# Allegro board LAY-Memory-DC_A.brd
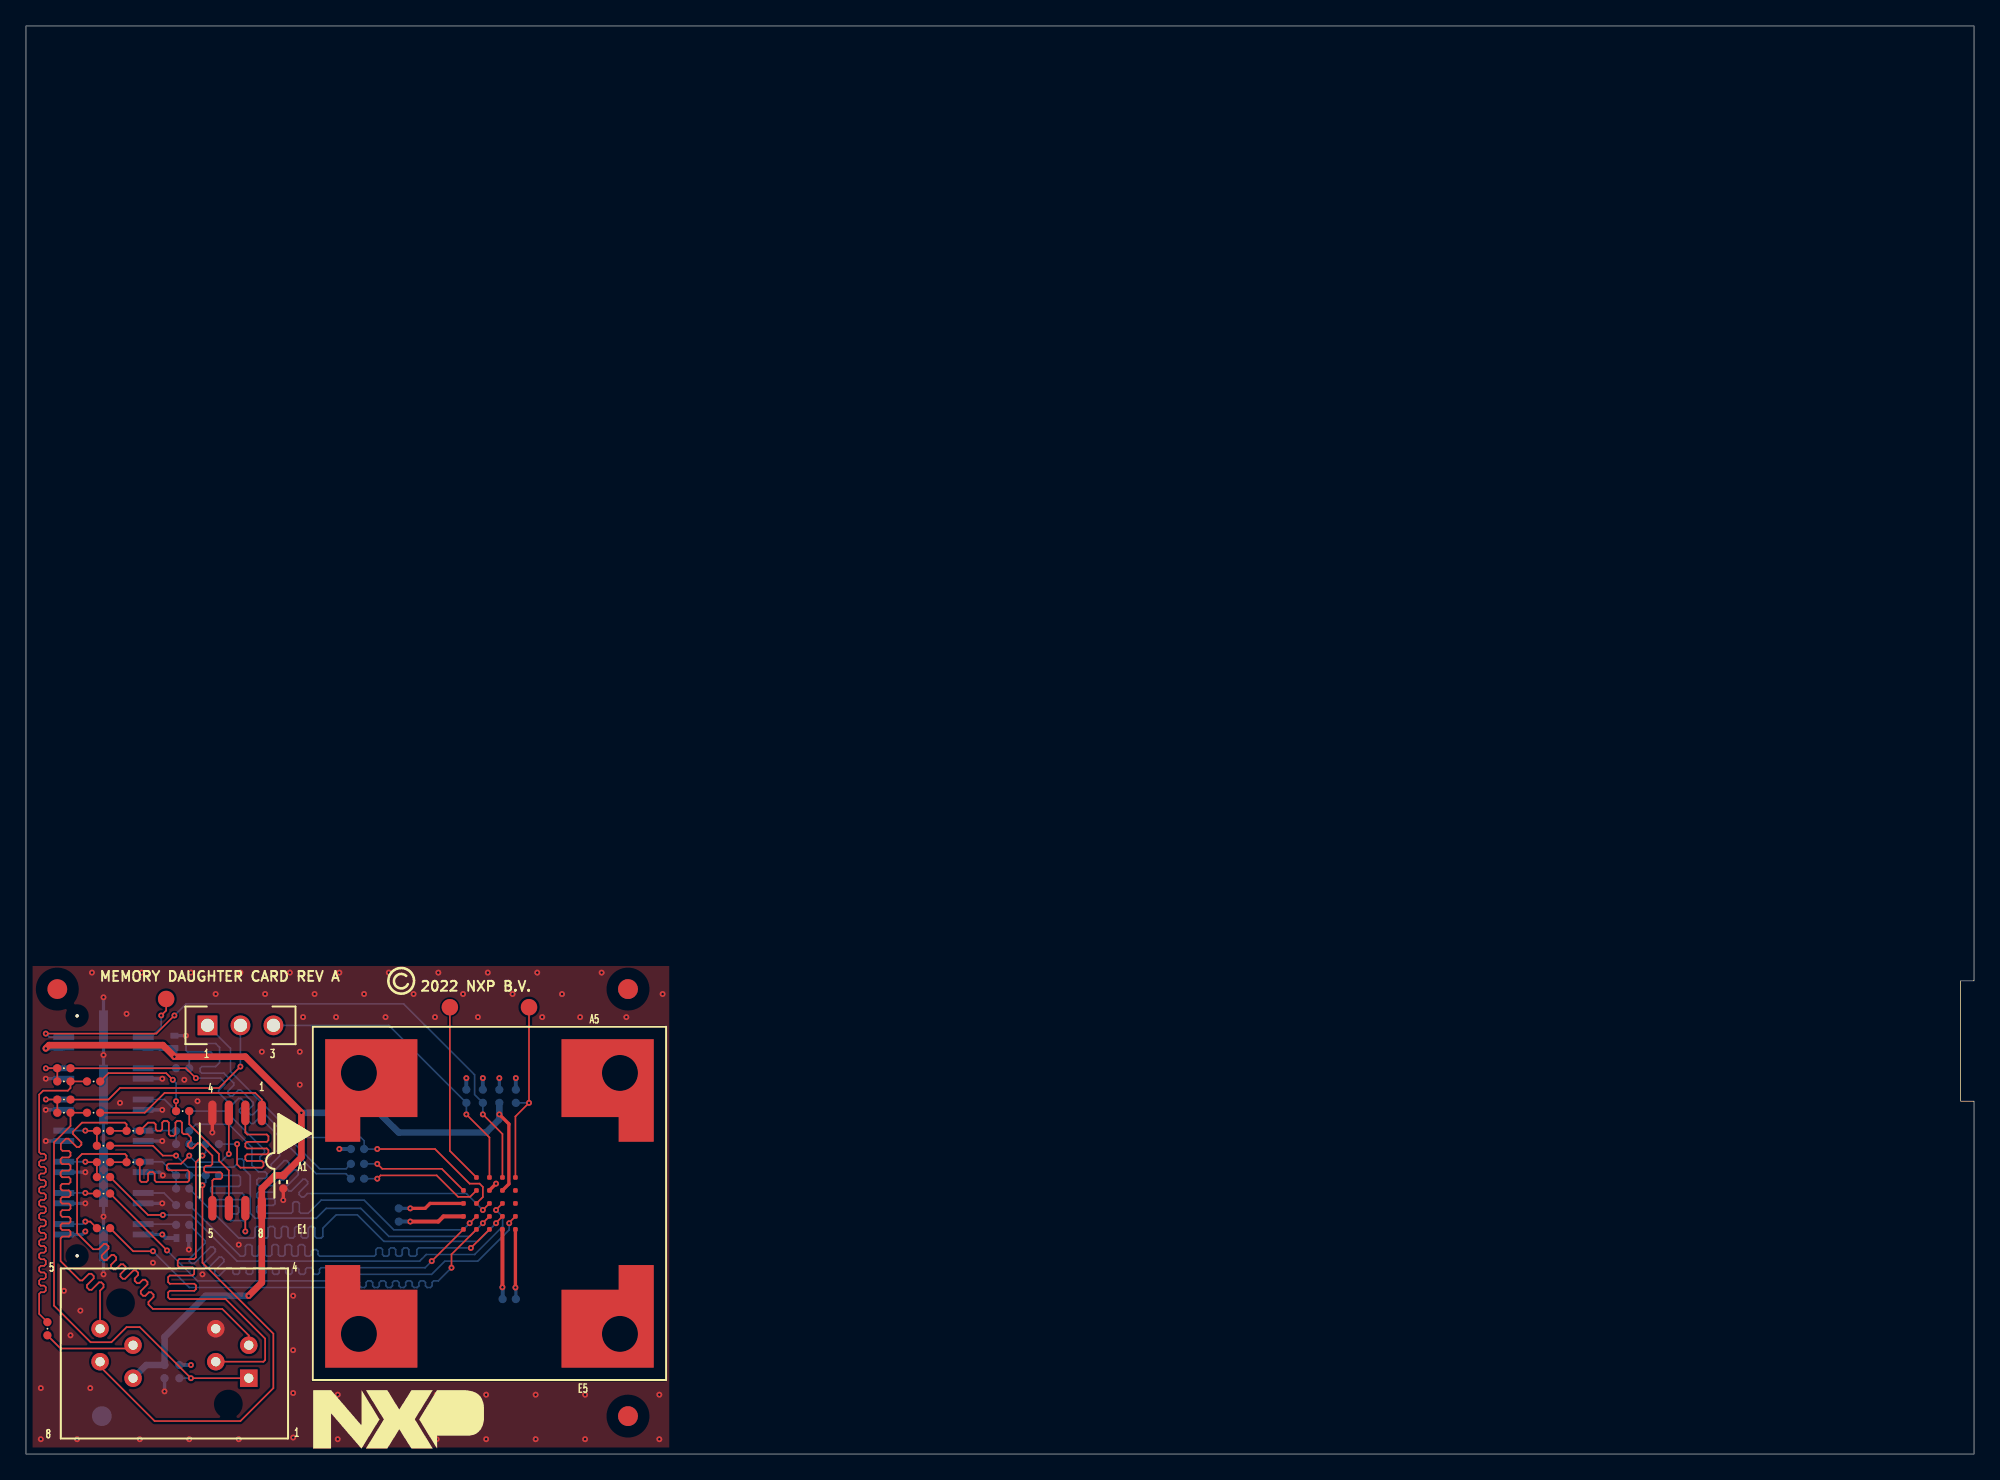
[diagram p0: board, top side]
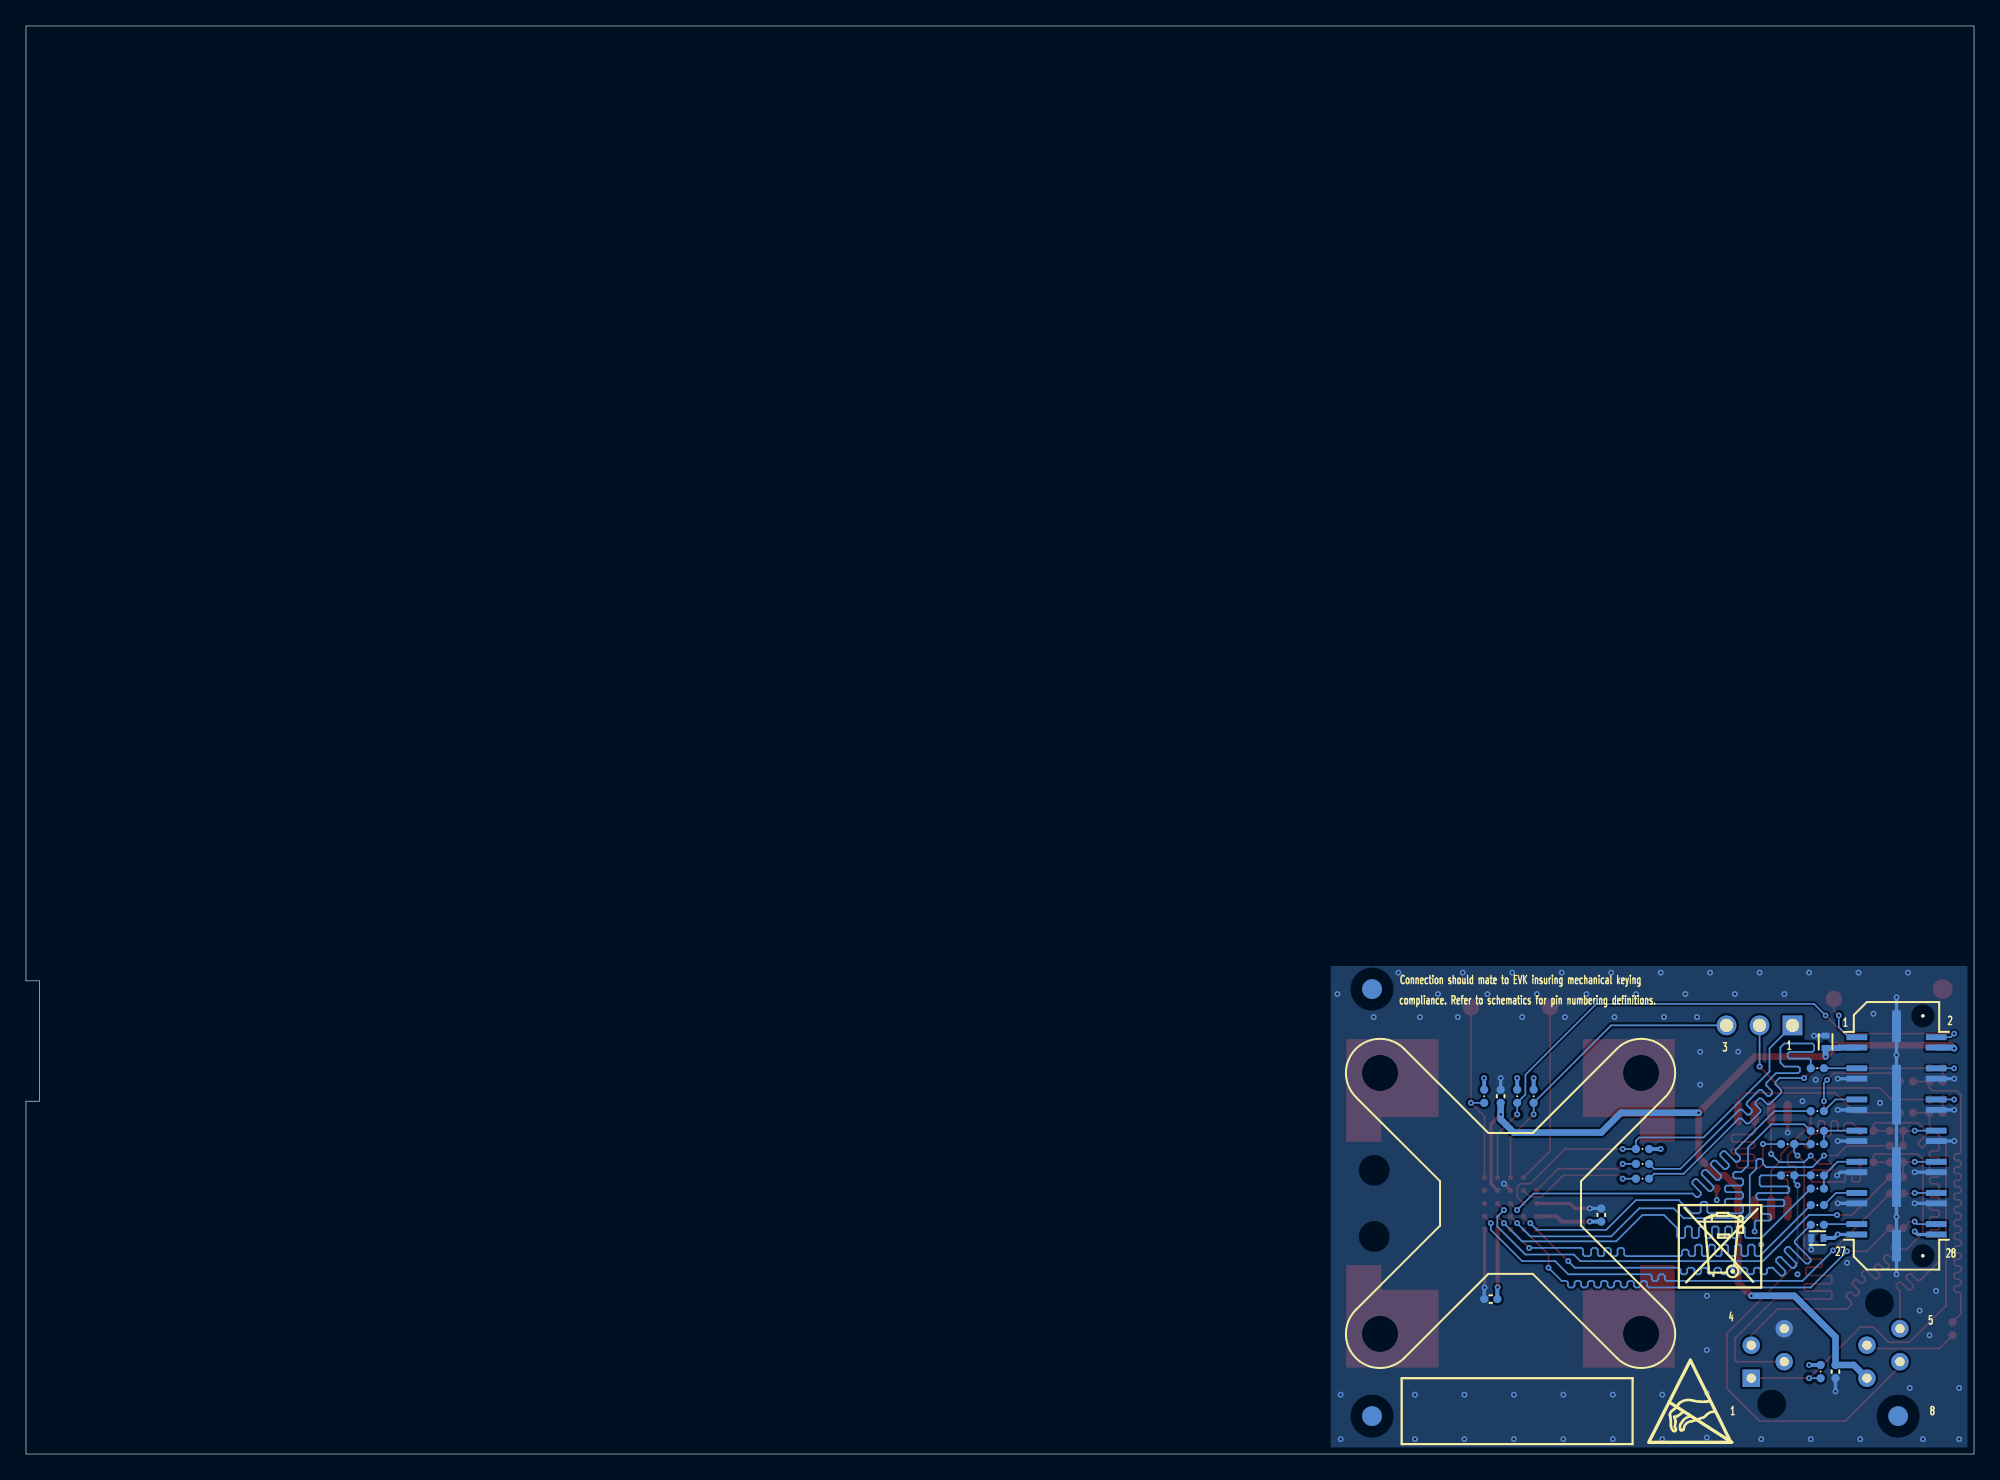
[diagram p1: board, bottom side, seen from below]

Outline 150 x 110 mm; copper layers: TOP, GND, POWER, BOTTOM. Coordinates in mm from the lower left corner of the outline.
Outline path: 0,110 150,110 150,36.45 148.97,36.45 148.97,27.18 150,27.18 150,0 0,0 0,110

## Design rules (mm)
constraint set DEFAULT: min track width 0.127
net group POWER: nets VDD_MEM VPP
net group SPI_D4: nets SPI_D4 SPI_D4_BGA24
net group SPI_D5: nets SPI_D5 SPI_D5_BGA24
net group SPI_D6: nets SPI_D6 SPI_D6_BGA24
net group SPI_D7: nets SPI_D7 SPI_D7_BGA24
net group SPI_DQS: nets SPI_DQS SPI_DQS_BGA24
net group 3W: nets RSTO#
net group SPI_CLK: nets N50940402 N50947464 N50953647 SPI_CLK SPI_CLK_BGA24 SPI_CLK_SD SPI_CLK_SOIC
net group SPI_CLKN: nets N50940399 SPI_CLKN SPI_CLKN_BGA24
net group SPI_CONN: nets CS_RAMN CSN_FLASH INT# SPI_RESETN
net group SPI_CSN_SD: nets SPI_CS_BGA24 SPI_CSN SPI_CSN_SD SPI_CSN_SOIC
net group SPI_D0: nets SPI_D0 SPI_D0_BGA24 SPI_D0_SD SPI_D0_SOIC
net group SPI_D1: nets SPI_D1 SPI_D1_BGA24 SPI_D1_SD SPI_D1_SOIC
net group SPI_D2: nets SPI_D2 SPI_D2_BGA24 SPI_D2_SD SPI_D2_SOIC
net group SPI_D3: nets SPI_D3 SPI_D3_BGA24 SPI_D3_SD SPI_D3_SOIC

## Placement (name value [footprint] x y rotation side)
C1  10uF  [CC0402_TOL0P2]  11.43 31.75 90 bottom
C2  10uF  [CC0402_TOL0P2]  12.06 16.64 0 bottom
C3  0.1UF  [CC0402_25]  28.7 18.41 90 bottom
C4  0.1UF  [CC0402_25]  37.21 11.94 0 bottom
C5  0.1UF  [CC0402_25]  36.45 27.56 90 bottom
C6  0.1UF  [CC0402_25]  10.67 6.35 270 bottom
C7  0.1UF  [CC0402_25]  19.81 20.95 270 top
J1  CON 2X14  [CON_28M_0P8_SMT]  5.97 24.51 270 bottom
JP1  HDR TH 1X3  [HDR103]  13.98 33.02 90 top
NOREF  -  []  9.88 31.15 90 top
NOREF#2  -  []  -4.81 5.8 0 top
NOREF#3  -  []  9.02 24.11 90 top
NOREF#4  -  []  33.69 17.3 0 top
NOREF#5  -  [unnamed#2]  2.41 35.81 0 top
NOREF#6  -  []  -2.26 -18.65 90 top
NOREF#7  -  []  30.44 17.52 0 top
NOREF#8  -  []  9.88 31.15 0 top
NOREF#9  -  []  11.59 16.64 0 top
NOREF#10  -  []  5.97 27.69 90 top
NOREF#11  -  []  22.12 0.42 0 top
NOREF#12  -  []  25.64 9.25 0 top
NOREF#13  -  []  2.91 16.91 0 top
NOREF#14  -  []  5.97 16.07 90 top
NOREF#15  -  []  11.43 31.28 90 top
NOREF#16  -  []  0 0 90 top
NOREF#17  -  []  50.51 1.01 90 top
NOREF#18  -  []  3.94 33.75 0 top
NOREF#19  -  [unnamed#2]  46.35 35.81 0 top
NOREF#20  -  []  -2.26 6.65 0 top
NOREF#21  -  []  11.47 16.99 0 top
NOREF#22  -  []  22.11 28.42 90 top
NOREF#23  -  []  -4.81 -21.2 90 top
NOREF#24  -  []  3.94 15.27 90 top
NOREF#25  -  []  3.94 15.27 90 top
NOREF#26  -  []  5.97 21.34 90 top
NOREF#27  -  []  2.86 29.42 0 top
NOREF#28  -  []  12.66 16.29 90 top
NOREF#29  -  []  0 0 0 top
NOREF#30  -  []  28.89 36.42 0 top
NOREF#31  -  []  45.74 9.25 90 top
NOREF#32  -  []  25.19 16.75 90 top
NOREF#33  -  []  25.19 16.75 0 top
NOREF#34  -  []  -219.71 -78.11 0 top
NOREF#35  -  []  9.02 16.91 90 top
NOREF#36  -  [unnamed#2]  46.35 2.92 0 top
NOREF#37  -  []  0 0.03 0 top
NOREF#38  -  [unnamed#2]  46.35 2.92 180 bottom
NOREF#39  -  []  22.73 12.83 180 bottom
NOREF#40  -  [unnamed#2]  46.35 35.81 180 bottom
NOREF#41  -  []  44.07 0.76 180 bottom
NOREF#42  -  []  25.02 0.9 180 bottom
NOREF#43  -  [unnamed#2]  5.84 2.92 180 bottom
R1  4.7K  [RC0402_25]  35.18 27.56 90 bottom
R2  4.7K  [RC0402_25]  25.53 23.5 180 bottom
R3  4.7K  [RC0402_25]  37.72 27.56 90 bottom
R4  4.7K  [RC0402_25]  33.91 27.56 90 bottom
R5  0  [RC0402_25]  25.53 21.21 180 bottom
R6  0  [RC0402_25]  25.53 22.35 180 bottom
R7  0  [RC0402_25]  1.65 9.65 90 top
R8  0  [RC0402_25]  12.06 26.42 180 top
R9  0  [RC0402_25]  2.92 27.3 180 top
R10  0  [RC0402_25]  2.92 29.72 180 top
R11  0  [RC0402_25]  12.06 29.72 180 bottom
R12  0  [RC0402_25]  12.06 26.42 180 bottom
R13  0  [RC0402_25]  5.97 23.75 180 top
R14  0  [RC0402_25]  12.06 24.89 180 bottom
R15  0  [RC0402_25]  5.97 21.34 180 top
R16  0  [RC0402_25]  12.06 20.45 180 bottom
R17  0  [RC0402_25]  5.97 20.07 180 top
R18  0  [RC0402_25]  12.06 19.18 180 bottom
R19  0  [RC0402_25]  5.97 17.4 180 top
R20  0  [RC0402_25]  12.06 17.65 180 bottom
R21  0  [RC0402_25]  2.92 28.7 180 top
R22  0  [RC0402_25]  2.92 26.29 180 top
R23  0  [RC0402_25]  5.97 24.89 180 top
R24  0  [RC0402_25]  12.06 23.88 180 bottom
R25  0  [RC0402_25]  5.97 22.48 180 top
R26  0  [RC0402_25]  12.06 21.46 180 bottom
R27  0  [RC0402_25]  5.21 28.7 180 top
R28  0  [RC0402_25]  5.21 26.29 180 top
R29  0  [RC0402_25]  8.26 24.89 180 top
R30  0  [RC0402_25]  14.35 23.88 180 bottom
R31  0  [RC0402_25]  8.26 22.48 180 top
R32  0  [RC0402_25]  14.35 21.46 180 bottom
R33  4.7K  [RC0402_25]  11.81 6.35 90 bottom
TP1  -  [TPAD_050]  10.79 35.05 0 top
TP2  -  [TPAD_050]  32.64 34.42 270 top
TP3  -  [TPAD_050]  38.73 34.42 270 top
U1  SUBASSEMBLY  [SKT_BGA24_1MM_25X25MM]  35.69 19.3 0 top
U2  SKT_SOP8+IS25WP064AJBLE  [SKT8_SOP_1P27_TH]  17.16 5.84 0 top
U3  IS25WP064AJBLE  [SO8-25X75-200]  16.26 22.61 180 top

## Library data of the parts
C1 C2 = CAP_NP: signal model: DEFAULT_CAPACITOR_1e+07pF_2_1
C3-C7 = CAP_NP: signal model: DEFAULT_CAPACITOR_100000pF_2_1
J1 = QSE_014_DP
JP1 = CONN_HDR_3X1
R1-R4 = RES
R5-R32 = RES: signal model: DEFAULT_RESISTOR_0.001OHM_2_1
R33 = RES: signal model: DEFAULT_RESISTOR_4700OHM_2_1
TP1-TP3 = TEST POINT L
U1 = MT35XU512ABA1G12
U2 U3 = 25WP_8P

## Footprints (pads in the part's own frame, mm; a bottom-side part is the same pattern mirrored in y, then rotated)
CC0402_25
  round 0.635 smd: 1(-0.508,0) 2(0.508,0)
CC0402_TOL0P2
  rect 0.457x0.61 smd: 1(-0.475,0) 2(0.475,0)
CON_28M_0P8_SMT
  round 0.254 hole 1.016 unplated: (-9.24,2.03) (9.24,2.03)
  rect 0.457x1.6 smd: 1(-7.6,-3.055) 2(-7.6,3.055) 3(-6.8,-3.055) 4(-6.8,3.055) 5(-5.2,-3.055) 6(-5.2,3.055) 7(-4.4,-3.055) 8(-4.4,3.055) 9(-2.8,-3.055) 10(-2.8,3.055) 11(-2,-3.055) 12(-2,3.055) 13(-0.4,-3.055) 14(-0.4,3.055) 15(0.4,-3.055) 16(0.4,3.055) 17(2,-3.055) 18(2,3.055) 19(2.8,-3.055) 20(2.8,3.055) 21(4.4,-3.055) 22(4.4,3.055) 23(5.2,-3.055) 24(5.2,3.055) 25(6.8,-3.055) 26(6.8,3.055) 27(7.6,-3.055) 28(7.6,3.055)
  rect 2.438x0.686 smd: SH1(-8.445,0) SH4(8.445,0)
  rect 4.597x0.686 smd: SH2(-3.175,0) SH3(3.175,0)
HDR103
  rect 1.524x1.524 hole 1.016: 1(0,0)
  round 1.524 hole 1.016: 2(0,-2.54) 3(0,-5.08)
RC0402_25
  round 0.635 smd: 1(-0.508,0) 2(0.508,0)
SKT8_SOP_1P27_TH
  round 0 hole 1.6 unplated: (-9.875,5.805) (-1.575,-1.995)
  rect 1.346x1.346 hole 0.711: 1(0,0)
  round 1.346 hole 0.711: 2(-2.54,1.27) 3(0,2.54) 4(-2.54,3.81) 5(-11.45,3.81) 6(-8.91,2.54) 7(-11.45,1.27) 8(-8.91,0)
SKT_BGA24_1MM_25X25MM
  round 0 hole 1.6 unplated: (-10.5,-2.55) (10.5,2.55) (10.5,-2.55)
  round 0 hole 2.007 unplated: (-10.05,10.05) (-10.05,-10.05) (10.05,10.05) (10.05,-10.05)
  custom 0.089x0.089 smd: A2(-1,2) A3(0,2) A4(1,2) A5(2,2) B1(-2,1) B2(-1,1) B3(0,1) B4(1,1) B5(2,1) C1(-2,0) C2(-1,0) C3(0,0) C4(1,0) C5(2,0) D1(-2,-1) D2(-1,-1) D3(0,-1) D4(1,-1) D5(2,-1) E1(-2,-2) E2(-1,-2) E3(0,-2) E4(1,-2) E5(2,-2)
SO8-25X75-200
  oval 0.635x1.905 smd: 1(-1.905,-3.67) 2(-0.635,-3.67) 3(0.635,-3.67) 4(1.905,-3.67) 5(1.905,3.67) 6(0.635,3.67) 7(-0.635,3.67) 8(-1.905,3.67)
TPAD_050
  round 1.27 smd: 1(0,0)
unnamed#2
  round 1.524 smd: (0,0)

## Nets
GND: C1.2 C2.2 C3.2 C4.2 C5.2 C6.2 C7.2 J1.7 J1.8 J1.11 J1.12 J1.15 J1.16 J1.19 J1.20 J1.23 J1.24 J1.SH1 J1.SH2 J1.SH3 J1.SH4 U1.B3 U1.C1 U1.E5(VSS3) U2.4 U3.4
VDD_MEM: C1.1 C5.1 C6.1 C7.1 J1.3 J1.4 U1.B4 U2.8 U3.8
VDDQ_MEM: C2.1 C3.1 C4.1 J1.27 J1.28 R1.2 R2.2 R3.2 R4.2 R33.2 U1.D1 U1.E4
CS_RAMN: JP1.3 R4.1 U1.A3
CSN_FLASH: JP1.1 R2.1 U1.C2
INT#: R3.1 TP3.1(TP) U1.A5
RSTO#: TP2.1(TP) U1.A2
SPI_CLK: J1.6 R10.2 R21.2
SPI_CLK_BGA24: R5.2 R10.1
SPI_CLK_SD: R8.2 R27.1
SPI_CLK_SOIC: R7.2 R21.1 R27.2
SPI_CLKN: J1.5 R11.2
SPI_CLKN_BGA24: R6.2 R11.1
SPI_CS_BGA24: JP1.2 R9.1
SPI_CSN: J1.10 R9.2 R22.2
SPI_CSN_SD: R28.1 U3.1
SPI_CSN_SOIC: R22.1 R28.2 R33.1 U2.1
SPI_D0: J1.14 R13.2 R23.2
SPI_D0_BGA24: R13.1 U1.D3
SPI_D0_SD: R29.1 U3.5
SPI_D0_SOIC: R23.1 R29.2 U2.5
SPI_D1: J1.13 R14.2 R24.2
SPI_D1_BGA24: R14.1 U1.D2
SPI_D1_SD: R30.1 U3.2
SPI_D1_SOIC: R24.1 R30.2 U2.2
SPI_D2: J1.18 R15.2 R25.2
SPI_D2_BGA24: R15.1 U1.C4
SPI_D2_SD: R31.1 U3.3(W\P\_IO2)
SPI_D2_SOIC: R25.1 R31.2 U2.3(W\P\_IO2)
SPI_D3: J1.17 R16.2 R26.2
SPI_D3_BGA24: R16.1 U1.D4
SPI_D3_SD: R32.1 U3.7
SPI_D3_SOIC: R26.1 R32.2 U2.7
SPI_D4: J1.22 R17.2
SPI_D4_BGA24: R17.1 U1.D5
SPI_D5: J1.21 R18.2
SPI_D5_BGA24: R18.1 U1.E3
SPI_D6: J1.26 R19.2
SPI_D6_BGA24: R19.1 U1.E2
SPI_D7: J1.25 R20.2
SPI_D7_BGA24: R20.1 U1.E1
SPI_DQS: J1.9 R12.2
SPI_DQS_BGA24: R12.1 U1.C3
SPI_ECC: J1.1 TP1.1(TP)
SPI_RESETN: J1.2 R1.1 U1.A4
VPP: U1.C5
N50940399: R6.1 U1.B1
N50940402: R5.1 U1.B2
N50947464: R7.1 U2.6
N50953647: R8.1 U3.6

Pads without a net: U1 B5

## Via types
v1: diameter 0.457, hole 0.203, TOP to BOTTOM, 142 vias

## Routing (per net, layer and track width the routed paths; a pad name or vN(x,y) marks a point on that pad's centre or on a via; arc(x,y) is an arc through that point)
GND: length 53.7
  TOP w0.254: v1(36.2,20.83) 35.69,20.32 U1.B3 ; U3.4 v1(14.35,24.77) ; U1.C1 31.11,19.3 30.73,18.92 v1(29.59,18.92) ; U1.E5 v1(37.69,12.83) ; C7.2 v1(19.81,19.56)
  BOTTOM w0.254: J1.19 10.29,21.71 v1(10.54,21.46) ; J1.23 v1(10.5,19.31) ; C5.2 v1(36.45,28.96) ; C4.2 37.72,12.79 v1(37.69,12.83) ; J1.7 v1(10.5,28.91) ; v1(1.52,26.51) 2.91,26.51 J1.12 ; C1.2 v1(12.32,32.22) ; v1(5.97,35.18) J1.SH1 v1(5.97,30.73) J1.SH2 J1.SH3 v1(5.97,18.29) v1(5.97,13.84) ; v1(4.57,21.71) J1.20 ; J1.11 v1(10.5,26.51) ; C3.2 v1(29.59,18.92) ; J1.24 v1(4.57,19.31) ; v1(1.52,24.11) 2.91,24.11 J1.16 ; J1.15 v1(10.5,24.11) ; C6.2 v1(10.67,4.83) ; C2.2 v1(12.54,15.75) ; J1.8 v1(1.52,28.91)
  vias: v1(1.14,5.08) v1(1.14,1.14) v1(2.92,12.57) v1(3.43,9.14) v1(3.94,1.14) v1(4.19,11.05) v1(4.95,5.08) v1(5.08,37.08) v1(7.24,27.05) v1(7.75,33.91) v1(8.76,1.14) v1(8.89,37.08) v1(9.78,14.73) v1(12.19,28.83) v1(12.57,1.14) v1(12.7,37.08) v1(13.21,27.18) v1(13.59,13.84) v1(14.61,35.43) v1(16.38,16.13) v1(16.38,1.14) v1(16.51,37.08) v1(18.16,30.99) v1(18.41,35.43) v1(20.32,37.08) v1(20.57,12.19) v1(20.57,8) v1(20.57,4.7) v1(20.57,1.27) v1(21.08,30.99) v1(21.08,28.45) v1(21.34,33.66) v1(22.23,35.43) v1(23.88,33.66) v1(24,4.57) v1(24,1.14) v1(24.13,37.08) v1(26.04,35.43) v1(27.69,33.66) v1(27.81,4.57) v1(27.81,1.14) v1(27.94,37.08) v1(29.84,35.43) v1(31.5,33.66) v1(31.62,4.57) v1(31.62,1.14) v1(31.75,37.08) v1(33.66,35.43) v1(34.8,33.66) v1(35.43,4.57) v1(35.43,1.14) v1(35.56,37.08) v1(37.47,35.43) v1(39.24,4.57) v1(39.24,1.14) v1(39.37,37.08) v1(39.75,33.66) v1(41.27,35.43) v1(42.67,33.66) v1(43.05,4.57) v1(43.05,1.14) v1(44.32,37.08) v1(46.23,33.66) v1(48.77,4.57) v1(48.77,1.14) v1(49.02,35.43)
VDD_MEM: length 79.3
  TOP w0.254: U1.B4 37.19,20.8 37.19,25.43 v1(36.45,26.16)
  TOP w0.508: v1(17.14,12.19) 18.16,13.21 U3.8 18.16,20.45 19.18,21.46 19.81,21.46 21.21,22.86 v1(21.21,26.29) 16.89,30.61 v1(11.43,30.61) 10.54,31.5 1.78,31.5 v1(1.52,31.24)
  BOTTOM w0.457: v1(1.52,31.24) 1.59,31.31 J1.4 ; v1(11.43,30.61) C1.1 10.39,31.28 10.36,31.31 J1.3
  BOTTOM w0.508: v1(21.21,26.29) 27.18,26.29 28.7,24.77 35.43,24.77 36.45,25.78 v1(36.45,26.16) C5.1 ; v1(17.14,12.19) 13.84,12.19 10.67,9.02 C6.1 9.26,6.86 U2.8
VDDQ_MEM: length 19.4
  TOP w0.305: U1.E4 v1(36.69,12.84) ; U1.D1 32.15,18.3 31.75,17.91 v1(29.59,17.91)
  BOTTOM w0.254: J1.28 4.34,16.91 v1(4.57,17.14) ; J1.27 v1(10.5,16.91)
  BOTTOM w0.305: R4.2 v1(33.91,28.96) ; C3.1 v1(29.59,17.91) ; R3.2 v1(37.72,28.96) ; R2.2 v1(24.13,23.5) ; R33.2 v1(12.7,6.86) ; C2.1 10.77,16.64 v1(10.5,16.91) ; R1.2 v1(35.18,28.96) ; 36.7,11.94 36.7,12.83 v1(36.69,12.84)
CS_RAMN: length 23.8
  TOP w0.127: v1(33.91,26.16) 35.69,24.38 U1.A3
  BOTTOM w0.127: v1(33.91,26.16) R4.1 27.94,33.02 JP1.3
CSN_FLASH: length 29.2
  TOP w0.127: v1(27.05,23.5) 31.5,23.5 34.16,20.83 34.92,20.83 35.18,20.57 35.18,19.8 U1.C2
  BOTTOM w0.127: JP1.1 15.75,31.25 15.75,29.46 20.83,24.38 25.78,24.38 26.04,24.13 R2.1 v1(27.05,23.5)
INT#: length 14.6
  TOP w0.127: TP3.1 v1(38.73,27.05) 37.69,26 U1.A5
  BOTTOM w0.127: R3.1 v1(38.73,27.05)
RSTO#: length 14
  TOP w0.127: U1.A2 32.64,23.35 TP2.1
SPI_CLK: length 3.3
  TOP w0.127: v1(1.53,29.71) 1.54,29.72 R10.2 R21.2
  BOTTOM w0.127: J1.6 v1(1.53,29.71)
SPI_CLK_BGA24: length 27.9
  TOP w0.127: R10.1 12.32,29.72 v1(13.08,28.96)
  BOTTOM w0.127: R5.2 24.64,21.59 22.35,21.59 18.09,25.85 17.91,25.85 17.52,25.46 17.34,25.46 16.44,26.36 16.44,26.54 16.83,26.93 16.83,27.11 16.55,27.39 16.37,27.39 15.91,26.94 15.73,26.94 14.83,27.84 14.83,28.02 15.29,28.47 15.29,28.65 14.99,28.96 v1(13.08,28.96)
SPI_CLK_SD: length 8.6
  TOP w0.127: R8.2 v1(11.56,27.18) ; R27.1 6.35,29.34 10.79,29.34 v1(11.3,28.83)
  BOTTOM w0.127: v1(11.56,27.18) 11.56,28.57 v1(11.3,28.83)
SPI_CLK_SOIC: length 30.1
  TOP w0.127: R7.2 1.02,10.79 1.02,12.34 1.14,12.46 1.4,12.46 1.52,12.59 1.52,12.84 1.4,12.97 1.14,12.97 1.02,13.1 1.02,13.35 1.14,13.48 1.4,13.48 1.52,13.61 1.52,13.86 1.4,13.99 1.14,13.99 1.02,14.11 1.02,14.37 1.14,14.49 1.4,14.49 1.52,14.62 1.52,14.88 1.4,15 1.14,15 1.02,15.13 1.02,15.38 1.14,15.51 1.4,15.51 1.52,15.64 1.52,15.89 1.4,16.02 1.14,16.02 1.02,16.15 1.02,16.4 1.14,16.53 1.4,16.53 1.52,16.65 1.52,16.91 1.4,17.03 1.14,17.03 1.02,17.16 1.02,17.42 1.14,17.54 1.4,17.54 1.52,17.67 1.52,17.92 1.4,18.05 1.14,18.05 1.02,18.18 1.02,18.43 1.14,18.56 1.4,18.56 1.52,18.69 1.52,18.94 1.4,19.07 1.14,19.07 1.02,19.19 1.02,19.45 1.14,19.57 1.4,19.57 1.52,19.7 1.52,19.96 1.4,20.08 1.14,20.08 1.02,20.21 1.02,20.46 1.14,20.59 1.4,20.59 1.52,20.72 1.52,20.97 1.4,21.1 1.14,21.1 1.02,21.23 1.02,21.48 1.14,21.61 1.4,21.61 1.52,21.73 1.52,21.99 1.4,22.11 1.14,22.11 1.02,22.24 1.02,22.5 1.14,22.62 1.4,22.62 1.52,22.75 1.52,23 1.4,23.13 1.14,23.13 1.02,23.26 1.02,27.69 1.32,27.99 3.23,27.99 3.43,28.19 R21.1 R27.2
SPI_CLKN: length 2.5
  BOTTOM w0.127: J1.5 11.55,29.71 R11.2
SPI_CLKN_BGA24: length 28.8
  BOTTOM w0.127: R6.2 24.64,21.97 22.61,21.97 18.04,26.53 17.86,26.53 17.47,26.14 17.29,26.14 17.11,26.32 17.11,26.5 17.5,26.89 17.5,27.07 16.54,28.04 16.36,28.04 15.9,27.58 15.72,27.58 15.54,27.76 15.54,27.94 16,28.4 16,28.58 15.24,29.34 13.54,29.34 13.41,29.46 13.41,29.72 13.54,29.84 14.61,29.84 14.91,30.15 14.91,31.32 14.61,31.62 12.45,31.62 12.32,31.5 12.32,31.1 12.45,30.97 14.22,30.97 14.35,30.84 14.35,30.59 14.22,30.46 12.7,30.46 12.57,30.33 R11.1
SPI_CS_BGA24: length 17.3
  TOP w0.127: v1(16.51,29.84) 14.86,28.19 7.24,28.19 6.35,27.3 R9.1
  BOTTOM w0.127: v1(16.51,29.84) 16.51,33.01 JP1.2
SPI_CSN: length 3.3
  TOP w0.127: R22.2 R9.2 1.54,27.3 v1(1.53,27.31)
  BOTTOM w0.127: J1.10 v1(1.53,27.31)
SPI_CSN_SD: length 14.3
  TOP w0.127: R28.1 9.14,26.29 10.67,27.81 17.65,27.81 18.16,27.3 U3.1
SPI_CSN_SOIC: length 35.8
  TOP w0.127: U2.1 v1(12.7,5.84) 8.76,9.78 7.75,9.78 6.58,8.61 4.98,8.61 2.16,11.43 2.16,24 3.43,25.27 R22.1 R28.2
  BOTTOM w0.127: R33.1 v1(12.7,5.84)
SPI_D0: length 3.7
  TOP w0.127: v1(4.57,24.91) 4.59,24.89 R23.2 R13.2
  BOTTOM w0.127: J1.14 v1(4.57,24.91)
SPI_D0_BGA24: length 36.1
  TOP w0.127: R13.1 9.78,23.75 10.54,22.99 v1(11.56,22.99) ; v1(35.18,17.78) 35.18,17.8 U1.D3
  BOTTOM w0.127: v1(35.18,17.78) 34.16,16.76 27.94,16.76 25.78,18.92 23.11,18.92 22.35,18.16 17.65,18.16 17.27,18.54 17.27,21.46 16.76,21.97 16.76,22.61 16.64,22.73 16.38,22.73 16.26,22.61 16.26,22.35 16,22.1 12.45,22.1 v1(11.56,22.99)
SPI_D0_SD: length 17.9
  TOP w0.127: U3.5 14.35,21.06 14.48,21.19 14.99,21.19 15.11,21.31 15.11,21.57 14.99,21.7 13.84,21.7 13.72,21.82 13.72,22.08 13.84,22.2 14.22,22.2 14.35,22.33 14.35,22.99 13.4,23.94 13.22,23.94 12.83,23.55 12.65,23.55 12.47,23.73 12.47,23.9 12.7,24.14 12.7,24.38 12.45,24.64 12.14,24.64 12.02,24.77 12.02,25.53 11.89,25.65 11.63,25.65 11.51,25.53 11.51,24.64 11.38,24.51 11.13,24.51 11,24.64 11,25.53 10.87,25.65 10.62,25.65 10.49,25.53 10.49,25.02 10.36,24.89 10.11,24.89 9.98,25.02 9.98,25.4 9.86,25.53 9.4,25.53 R29.1
SPI_D0_SOIC: length 36.9
  TOP w0.127: U2.5 5.71,12.58 5.97,12.85 5.97,13.06 5.81,13.22 5.63,13.22 5.06,12.65 4.88,12.65 4.7,12.83 4.7,13.01 5.21,13.53 5.21,13.71 5.03,13.89 4.85,13.89 4.34,13.37 4.16,13.37 2.67,14.86 2.67,16.62 2.79,16.75 3.3,16.75 3.43,16.88 3.43,17.13 3.3,17.26 2.79,17.26 2.67,17.38 2.67,17.64 2.79,17.77 3.3,17.77 3.43,17.89 3.43,18.15 3.3,18.27 2.79,18.27 2.67,18.4 2.67,18.65 2.79,18.78 3.3,18.78 3.43,18.91 3.43,19.16 3.3,19.29 2.79,19.29 2.67,19.42 2.67,19.67 2.79,19.8 3.3,19.8 3.43,19.92 3.43,20.18 3.3,20.31 2.79,20.31 2.67,20.43 2.67,20.69 2.79,20.81 3.3,20.81 3.43,20.94 3.43,21.19 3.3,21.32 2.79,21.32 2.67,21.45 2.67,21.7 2.79,21.83 3.3,21.83 3.43,21.96 3.43,22.21 3.3,22.34 2.79,22.34 2.67,22.46 2.67,22.72 2.79,22.85 3.3,22.85 3.43,22.97 3.43,23.23 3.3,23.35 2.81,23.35 2.69,23.48 2.69,23.9 3.08,24.29 3.26,24.29 3.91,23.65 4.09,23.65 4.27,23.83 4.27,24.01 3.62,24.65 3.62,24.83 4.32,25.53 7.62,25.53 7.75,25.4 R29.2 R23.1
SPI_D1: length 3.6
  BOTTOM w0.127: J1.13 11.54,24.91 R14.2 R24.2
SPI_D1_BGA24: length 37.3
  TOP w0.127: v1(34.16,17.78) U1.D2
  BOTTOM w0.127: v1(34.16,17.78) 33.66,17.27 28.32,17.27 26.04,19.56 22.73,19.56 21.72,18.54 21.18,18.54 21.05,18.67 21.05,19.3 20.92,19.43 20.67,19.43 20.54,19.3 20.54,18.67 20.41,18.54 17.91,18.54 17.78,18.67 17.78,19.03 17.91,19.16 19.05,19.16 19.18,19.28 19.18,19.54 19.05,19.66 17.91,19.66 17.78,19.79 17.78,20.04 17.91,20.17 19.05,20.17 19.18,20.3 19.18,20.55 19.05,20.68 17.91,20.68 17.78,20.81 17.78,21.1 17.91,21.23 18.41,21.23 18.54,21.36 18.54,21.61 18.41,21.74 17.91,21.74 17.4,22.24 17.4,23.62 15.62,25.4 13.08,25.4 R14.1
SPI_D1_SD: length 17
  TOP w0.127: U3.2 16.89,24.77 17.04,24.61 18.54,24.61 18.67,24.49 18.67,24.17 18.54,24.05 17.02,24.05 16.89,23.92 16.89,23.67 17.02,23.54 18.54,23.54 18.67,23.41 18.67,23.21 18.54,23.08 17.02,23.08 16.89,22.95 16.89,22.7 17.02,22.57 18.16,22.57 18.29,22.45 18.29,22.19 18.16,22.06 16.51,22.06 16.26,22.31 v1(16.26,23.88)
  BOTTOM w0.127: R30.1 v1(16.26,23.88)
SPI_D1_SOIC: length 35.9
  TOP w0.127: U2.2 18.29,7.11 18.41,7.24 18.41,8.89 15.37,11.94 11.07,11.94 10.95,12.06 10.95,12.45 11.07,12.57 12.96,12.57 13.09,12.7 13.09,12.99 12.96,13.12 11.07,13.12 10.95,13.24 10.95,13.63 11.07,13.75 12.83,13.75 12.95,13.88 12.95,14.26 12.83,14.39 11.81,14.39 11.68,14.51 11.68,14.9 11.81,15.02 12.95,15.02 13.08,15.15 13.08,22.48 v1(13.59,22.99)
  BOTTOM w0.127: R24.1 R30.2 13.84,23.24 v1(13.59,22.99)
SPI_D2: length 3.7
  TOP w0.127: R15.2 R25.2 4.6,22.48 v1(4.57,22.51)
  BOTTOM w0.127: J1.18 v1(4.57,22.51)
SPI_D2_BGA24: length 36.2
  TOP w0.127: U1.C4 36.2,18.81 v1(36.2,18.8) ; R15.1 9.4,18.41 v1(10.54,18.41)
  BOTTOM w0.127: v1(36.2,18.8) 36.7,18.29 36.7,17.53 34.54,15.37 30.82,15.37 30.31,14.86 16.26,14.86 12.7,18.41 v1(10.54,18.41)
SPI_D2_SD: length 18
  TOP w0.127: v1(12.57,22.99) 11.95,22.36 10.97,22.36 10.85,22.23 10.85,21.98 10.97,21.85 12.45,21.85 12.57,21.73 12.57,21.08 12.45,20.95 10.04,20.95 9.91,21.08 9.91,21.59 9.78,21.72 9.53,21.72 9.4,21.59 9.4,21.08 9.27,20.95 8.89,20.95 8.76,21.08 R31.1 ; U3.3 v1(15.62,23.11)
  BOTTOM w0.127: v1(15.62,23.11) 14.99,22.48 13.08,22.48 v1(12.57,22.99)
SPI_D2_SOIC: length 36.9
  TOP w0.127: R25.1 R31.2 7.75,22.99 7.62,23.11 4.32,23.11 3.94,22.73 3.94,17.02 5.18,15.77 5.59,15.77 5.99,16.18 6.17,16.18 6.35,16 6.35,15.82 5.84,15.3 5.84,15.12 6.01,14.94 6.19,14.94 6.59,15.33 6.77,15.33 6.95,15.15 6.95,14.97 6.55,14.58 6.55,14.4 6.73,14.22 6.91,14.22 7.31,14.61 7.48,14.61 7.66,14.43 7.66,14.25 7.27,13.86 7.27,13.68 7.45,13.5 7.63,13.5 8.28,14.15 8.46,14.15 8.64,13.97 8.64,13.79 8.37,13.52 8.37,13.34 8.55,13.16 8.73,13.16 9,13.43 9.18,13.43 9.36,13.25 9.36,13.07 8.84,12.55 8.84,12.37 9.02,12.19 9.2,12.19 9.46,12.46 9.64,12.46 9.82,12.28 9.82,12.1 9.43,11.71 9.43,11.53 9.78,11.18 15.11,11.18 17.16,9.13 U2.3
SPI_D3: length 4
  BOTTOM w0.127: R16.2 R26.2 10.51,22.51 J1.17
SPI_D3_BGA24: length 35.9
  TOP w0.127: U1.D4 36.2,17.81 v1(36.2,17.78)
  BOTTOM w0.127: R16.1 16.38,16.64 17.51,16.64 17.63,16.76 17.63,17.4 17.76,17.53 18.02,17.53 18.14,17.4 18.14,16.76 18.27,16.64 18.52,16.64 18.65,16.76 18.65,17.4 18.78,17.53 19.03,17.53 19.16,17.4 19.16,16.76 19.29,16.64 19.54,16.64 19.67,16.76 19.67,17.4 19.79,17.53 20.05,17.53 20.17,17.4 20.17,16.76 20.3,16.64 20.56,16.64 20.68,16.76 20.68,17.4 20.81,17.53 21.06,17.53 21.19,17.4 21.19,16.76 21.32,16.64 21.61,16.64 21.74,16.76 21.74,17.4 21.86,17.53 22.12,17.53 22.25,17.4 22.25,16.76 22.37,16.64 22.73,16.64 22.86,16.76 22.86,17.4 23.88,18.41 25.53,18.41 27.56,16.38 34.8,16.38 v1(36.2,17.78)
SPI_D3_SD: length 17.6
  TOP w0.127: U3.7 v1(16.89,17.14)
  BOTTOM w0.127: v1(16.89,17.14) 16.89,17.86 16.76,17.98 15.75,17.98 15.62,18.11 15.62,18.37 15.75,18.49 16.26,18.49 16.38,18.62 16.38,18.96 16.26,19.09 14.73,19.09 14.61,19.21 14.61,19.47 14.73,19.6 16.64,19.6 16.76,19.72 16.76,19.98 16.64,20.1 14.35,20.1 14.22,20.23 14.22,20.48 14.35,20.61 16.38,20.61 16.51,20.74 16.51,21.34 16.38,21.46 R32.1
SPI_D3_SOIC: length 36.5
  TOP w0.127: v1(13.59,20.7) 13.59,14.73 19.05,9.27 19.05,5.08 16.51,2.54 9.91,2.54 5.71,6.74 U2.7
  BOTTOM w0.127: R26.1 R32.2 13.84,20.95 v1(13.59,20.7)
SPI_D4: length 2.6
  TOP w0.127: R17.2 4.62,20.07 v1(4.57,20.11)
  BOTTOM w0.127: J1.22 v1(4.57,20.11)
SPI_D4_BGA24: length 37.2
  TOP w0.127: v1(37.21,17.78) 37.21,17.83 U1.D5 ; v1(10.86,15.68) R17.1
  BOTTOM w0.127: v1(10.86,15.68) 13.21,13.34 23.68,13.34 23.81,13.46 23.81,13.72 23.93,13.84 24.19,13.84 24.31,13.72 24.31,13.46 24.44,13.34 24.69,13.34 24.82,13.46 24.82,13.72 24.95,13.84 31.24,13.84 32.26,14.86 34.8,14.86 37.21,17.27 v1(37.21,17.78)
SPI_D5: length 2.9
  BOTTOM w0.127: J1.21 10.62,20.11 R18.2
SPI_D5_BGA24: length 36.9
  TOP w0.127: v1(34.26,15.88) U1.E3
  BOTTOM w0.127: v1(34.26,15.88) 30.23,15.88 30.1,15.75 30.1,15.37 29.97,15.24 29.61,15.24 29.48,15.37 29.48,15.75 29.36,15.88 29.1,15.88 28.97,15.75 28.97,15.37 28.85,15.24 28.59,15.24 28.47,15.37 28.47,15.75 28.34,15.88 28.09,15.88 27.96,15.75 27.96,15.37 27.83,15.24 27.58,15.24 27.45,15.37 27.45,15.75 27.32,15.88 27.07,15.88 26.94,15.75 26.94,15.37 26.82,15.24 22.61,15.24 22.49,15.37 22.49,15.62 22.36,15.75 22.1,15.75 21.98,15.62 21.98,15.37 21.85,15.24 21.6,15.24 21.47,15.37 21.47,16 21.34,16.13 21.09,16.13 20.96,16 20.96,15.37 20.83,15.24 20.58,15.24 20.45,15.37 20.45,16 20.33,16.13 20.07,16.13 19.95,16 19.95,15.37 19.82,15.24 19.56,15.24 19.44,15.37 19.44,16 19.31,16.13 19.06,16.13 18.93,16 18.93,15.37 18.8,15.24 18.55,15.24 18.42,15.37 18.42,16 18.29,16.13 18.04,16.13 17.91,16 17.91,15.37 17.79,15.24 17.53,15.24 17.41,15.37 17.41,16 17.28,16.13 17.02,16.13 16.9,16 16.9,15.37 16.77,15.24 16.51,15.24 R18.1
SPI_D6: length 2.8
  TOP w0.127: R19.2 4.95,17.91 v1(4.57,17.91)
  BOTTOM w0.127: J1.26 4.38,17.71 v1(4.57,17.91)
SPI_D6_BGA24: length 37
  TOP w0.127: R19.1 8.26,15.62 v1(9.78,15.62) ; v1(32.77,14.35) 32.77,15.38 U1.E2
  BOTTOM w0.127: v1(32.77,14.35) 31.75,13.34 31.4,13.34 31.27,13.21 31.27,12.95 31.14,12.83 30.89,12.83 30.76,12.95 30.76,13.21 30.63,13.34 30.38,13.34 30.25,13.21 30.25,12.95 30.13,12.83 29.87,12.83 29.74,12.95 29.74,13.21 29.62,13.34 29.36,13.34 29.24,13.21 29.24,12.95 29.11,12.83 28.86,12.83 28.73,12.95 28.73,13.21 28.6,13.34 28.35,13.34 28.22,13.21 28.22,12.95 28.09,12.83 27.84,12.83 27.71,12.95 27.71,13.21 27.59,13.34 27.33,13.34 27.2,13.21 27.2,12.95 27.08,12.83 26.82,12.83 26.7,12.95 26.7,13.21 26.57,13.34 26.32,13.34 26.19,13.21 26.19,12.95 26.06,12.83 25.81,12.83 25.68,12.95 25.68,13.21 25.55,13.34 25.3,13.34 25.17,13.21 25.17,12.95 25.05,12.83 12.57,12.83 v1(9.78,15.62)
SPI_D7: length 2.6
  BOTTOM w0.127: R20.2 11.5,17.71 J1.25
SPI_D7_BGA24: length 37.3
  TOP w0.127: v1(31.24,14.86) U1.E1
  BOTTOM w0.127: v1(31.24,14.86) 30.73,14.35 22.73,14.35 22.6,14.22 22.6,13.97 22.47,13.84 22.22,13.84 22.09,13.97 22.09,14.22 21.96,14.35 21.65,14.35 21.52,14.22 21.52,13.97 21.4,13.84 21.14,13.84 21.01,13.97 21.01,14.22 20.89,14.35 20.63,14.35 20.51,14.22 20.51,13.97 20.38,13.84 20.13,13.84 20,13.97 20,14.22 19.87,14.35 19.62,14.35 19.49,14.22 19.49,13.97 19.36,13.84 19.11,13.84 18.98,13.97 18.98,14.22 18.86,14.35 18.6,14.35 18.47,14.22 18.47,13.97 18.35,13.84 18.09,13.84 17.97,13.97 17.97,14.22 17.84,14.35 17.59,14.35 17.46,14.22 17.46,13.97 17.33,13.84 17.08,13.84 16.95,13.97 16.95,14.22 16.82,14.35 16.57,14.35 16.44,14.22 16.44,13.97 16.32,13.84 16.06,13.84 15.93,13.97 15.93,14.22 15.81,14.35 15.49,14.35 14.89,13.74 14.71,13.74 14.53,13.92 14.53,14.1 15.24,14.81 15.24,14.99 15.06,15.17 14.88,15.17 14.04,14.33 13.86,14.33 13.68,14.51 13.68,14.69 14.58,15.59 14.58,15.77 14.4,15.95 14.22,15.95 12.94,14.67 12.76,14.67 12.58,14.85 12.58,15.03 13.8,16.25 13.8,16.43 R20.1
SPI_DQS: length 2.9
  BOTTOM w0.127: R12.2 10.66,27.31 J1.9
SPI_DQS_BGA24: length 37
  TOP w0.127: v1(35.18,18.8) U1.C3
  BOTTOM w0.127: v1(35.18,18.8) 33.91,20.07 21.67,20.07 21.4,19.8 21.22,19.8 21.04,19.98 21.04,20.16 21.69,20.81 21.69,20.99 21.51,21.17 21.33,21.17 20.43,20.27 20.25,20.27 20.07,20.45 20.07,20.63 20.97,21.52 20.97,21.7 20.79,21.88 20.61,21.88 19.84,21.11 19.66,21.11 19.48,21.29 19.48,21.47 20.25,22.24 20.25,22.42 20.07,22.6 19.89,22.6 19.24,21.96 19.06,21.96 18.88,22.14 18.88,22.32 19.53,22.96 19.53,23.14 19.35,23.32 19.17,23.32 18.37,22.52 18.19,22.52 18.01,22.7 18.01,22.88 18.37,23.24 18.37,23.42 15.37,26.42 R12.1
SPI_ECC: length 4
  TOP w0.127: TP1.1 10.79,34.16 v1(10.41,33.78)
  BOTTOM w0.127: J1.1 9.63,32.11 10.41,32.89 v1(10.41,33.78)
SPI_RESETN: length 46.5
  TOP w0.127: v1(11.43,33.78) 10.03,32.38 v1(1.52,32.38) ; U1.A4 36.69,24.65 v1(35.18,26.16)
  BOTTOM w0.127: v1(1.52,32.38) 1.8,32.11 J1.2 ; v1(35.18,26.16) R1.1 34.54,27.69 34.54,29.21 29.08,34.67 12.32,34.67 v1(11.43,33.78)
N50940399: length 8.5
  TOP w0.127: v1(27.05,22.35) 27.43,21.97 32.02,21.97 U1.B1
  BOTTOM w0.127: v1(27.05,22.35) R6.1
N50940402: length 9.6
  TOP w0.127: U1.B2 34.2,19.81 33.27,19.81 31.62,21.46 27.3,21.46 v1(27.05,21.21)
  BOTTOM w0.127: R5.1 v1(27.05,21.21)
N50947464: length 7.1
  TOP w0.127: U2.6 7.99,8.13 2.67,8.13 R7.1
N50953647: length 8.7
  TOP w0.127: R8.1 12.57,25.4 14.86,23.11 14.86,22.61 15.62,21.84 U3.6

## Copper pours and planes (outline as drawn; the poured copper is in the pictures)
GND on TOP: 0.51,0.51 0.51,37.59 49.53,37.59 49.53,0.51 ; 4 cut-outs
GND on BOTTOM: 0.51,0.51 0.51,37.59 49.53,37.59 49.53,0.51 ; 2 cut-outs
GND on GND: 0.51,0.51 0.51,37.59 49.53,37.59 49.53,0.51
VDDQ_MEM on POWER: 0.51,0.51 0.51,37.59 49.53,37.59 49.53,0.51
Net_1 on TOP (solid shape): outline of 92 points within 41.24,6.65 48.34,14.55
Net_51 on TOP (solid shape): outline of 92 points within 41.24,24.05 48.34,31.95
Net_53 on TOP (solid shape): outline of 92 points within 23.04,24.05 30.14,31.95
Net_55 on TOP (solid shape): outline of 92 points within 23.04,6.65 30.14,14.55

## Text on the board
BOTTOM: 7 | ARTWORK BOTTOM
Ref Des/Silkscreen Bottom: Connection should mate to EVK insuring mechanical keying | compliance. Refer to schematics for pin numbering definitions. | 9 | SILKSCREEN BOTTOM
User.Comments: 3 | 8 | SOLDMASK BOTTOM | SOLDMASK TOP
TOP: 4 | ARTWORK TOP
Ref Des/Silkscreen Top: MEMORY DAUGHTER CARD REV A | 2 | SILKSCREEN TOP
GND: 5 | ARTWORK LAYER02
POWER: 6 | ARTWORK LAYER03
DIMENSION01: If the angle of PCB board outline is circular,please use this kind of break out area | If not use it,please delete it before you gerber out | If the angle of PCB board outline is right angle,please use this kind of break out area | AS usual,please use the 0.8MM stamp Via
XSECTION_CHART: *  SURFACE - AIR 0 MIL | L1 TOP CONDUCTOR - COPPER 1.8 MIL | *  DIELECTRIC - TU768 3.5 MIL | L2 GND PLANE - COPPER 1.2 MIL | *  DIELECTRIC - TU768 47.25 MIL | L3 INT1 PLANE - COPPER 1.2 MIL | L4 BOTTOM CONDUCTOR - COPPER 1.8 MIL | DESIGN CROSS SECTION CHART | ___________________________ | TOTAL THICKNESS 60.25 MIL | 1-4
DIMENSION: A_TARGET:3 MILS | B_TARGET:52 MILS | C_TARGET:3 MILS | SCALE: NONE | GRID ORIGIN | PRIMARY DATUM | .062" THK +/- 10% | LAYER 1  COMPONENT SIDE     1/2oz+plating | LAYER 2  GROUND PLANE       1 oz. | LAYER 3  POWER PLANE        1 oz. | LAYER 4  SOLDER SIDE        1/2oz+plating | FINISHED Cu WEIGHT | 0 | DETAIL A | LAYER STACKUP
BODY_CENTER: 19 | 8 | 16 | 22. THIS BOARD USES VIA-IN-PAD: SEE FAB_VIAFILL.ART | 21. THE MANUFACTURE HAS THE OPTION TO ADD COPPER THIEVING ON OUTER AND INNER LAYERS, | 9. SOLDERMASK - TO MEET THE REQUIREMENTS OF IPC-SM-840E (OR LATEST REVISION). | GREEN COLOR, BOTH SIDES. MODIFICATION OF SOLDERMASK IS NOT ALLOWED WITHOUT WRITTEN PERMISSION FROM NXP. | 7. PLATING FINISH: A. BOTH SIDES ENIG: TO MEET THE REQUIREMENTS OF IPC-4552 (LATEST REVISION). | 1. THIS DRAWING SPECIFIES THE REQUIREMENTS FOR A PRINTED WIRING BOARD IN ACCORDANCE. | WITH SPECIFICATION IPC-6012 CLASS 2 (LATEST REVISION). | 2. THE PWB MUST BE LEAD FREE ASSEMBLY PROCESS COMPATIBLE AND MUST BE ABLE TO HANDLE | A MINIMUM OF 5 CYCLES AT 260 DEGREES CELSIUS FOR 10 SECONDS. | 3. BASE MATERIAL - LAMINATE AND PREPREG SHALL MEET IPC-4101D-26, 83 or 98 | 4. COPPER FOIL WEIGHT - SEE STACKUP DETAIL 'A' | 5. CHARACTERISTIC IMPEDANCE - SEE DETAIL 'B' | 6. MINIMUM CONDUCTIVE WIDTH/SPACING TO BE .0042"/.005X" | 8. ALL THROUGH HOLE VIAS MAY BE PLATED SHUT. | 10. SILKSCREEN - WHITE EPOXY OR ACRYLIC INK, BOTH SIDES. NO SILKSCREEN ON ANY EXPOSED COPPER FEATURE. | 11. ELECTRICAL TEST - 100% IPCD356. PCB FABRICATOR TO PERFORM A NET COMPARE AGAINST THE IPCD356 NETLIST PROVIDED BY NXP. | 12. PRINTED WIRING BOARD IS TO BE INDIVIDUALLY BAGGED. | 13. DFM CHECK MUST BE RUN ON BOARD DATA BEFORE BUILDING BOARDS, | UNLESS PRIOR APPROVAL IS GIVEN IN WRITING BY NXP. | 14. TEARDROPS MAY BE ADDED AT THE FAB HOUSE TO ALL SIGNAL LAYERS. | 15. TWO SOLDER SAMPLES TO BE PROVIDED. | 16. SUPPLIER MARKINGS - ON SECONDARY SIDE ONLY, WHERE SHOWN. | 17. THE PWB WILL BE MARKED AS LEAD FREE BY USE OF AN INK STAMP Pb | 18. THE PWB WILL BE MARKED AS LEAD FREE PROCESS COMPATIBLE BY USE OF AN INK STAMP 260 C | 20. FINISHED PCB MUST BE PANELIZED FOR ASSEMBLY ACCORDING TO CONTRACT MANUFACTURERS REQUIREMENTS. | A. ALL VIAS USING X.1 DRILL SIZES ARE TO BE FILLED WITH NON-CONDUCTIVE VIA FILL. | B. OVERPLATE THE FILLED VIA AND APPLY FINISH METAL TREATMENT. | C. DIMPLE OR PROTRUSION ON VIA-IN-PADS MUST BE NO GREATER THAN .001". | KEEP A MINIMUM DISTANCE OF .100" FROM ANY BOARD FEATURES. | THE ADDITION OF RAILS AND .125" NON-PLATED TOOLING HOLES ARE AT THE DISCRETION OF | CONTRACT MANUFACTURER. PANELIZATION MUST BE APPROVED BY CONTRACT MANUFACTURER. | LACKWERKE-PETERS PP2795 OR EQUIVALENT AND MADE PLANAR TO THE PADS. | TYPE: LPI OR EQUIVALENT. | Tg - MUST BE GREATER THAN OR EQUAL TO 150 DEGREES CELSIUS. | Td - MUST BE GREATER THAN OR EQUAL TO 330 DEGREES CELSIUS. | - MUST BE UL RECOGNIZED AND MUST HAVE AN ID THAT CONFORMS TO UL94V-0 | A. LOCATION = +/-.002" OF PLATED PADS. | B. DIAMETER OR SIZE = +/-.002 OF ORIGINAL DATA | UNLESS OTHERWISE SPECIFIED. | 19. ALL PLATED AND NON-PLATED THROUGH HOLES ARE TO BE DRILLED AT PRIMARY DRILL STEP. | ALL HOLE LOCATION TOLERANCES ARE TO BE +/-.002 IN REFERENCE TO THE PRIMARY DATUM | 1 | DETAIL B | IMPEDANCE REQUIREMENTS | IMPEDANCE TOLERANCE IS 10%
PASTEMASK_BOTTOM: 10 | PASTEMASK_BOTTOM
User.6: 1 | PASTEMASK_TOP
User.12: 6501 WILLIAM CANNON DRIVE WEST | AUSTIN. TEXAS 78735 USA | SHEET | THIS DOCUMENT CONTAINS INFORMATION | PROPRIETARY TO FREESCALE AND SHALL | NOT BE USED FOR ENGINEERING DESIGN | PROCUREMENT OR MANUFACTURE IN WHOLE | OR IN PART WITHOUT THE CONSENT OF | NXP. | OF 10 | FILM | NAME | DATE | 02-15-22 | ___ PUBI (PUBLIC INFORMATION) | ___ FIUO (NXP INTERNAL USE ONLY) | ___ FCP (NXP CONFIDENTIAL PROPRIETARY) | NUMBER | X | MEMORY DAUGHTER CARD | 170-xxxxx     REV A | NXP SEMICONDUCTOR
User.13: 2 | THIS FAB_VIAFILL.ART SHOWS LOCATIONS OF VIA-IN-PAD TO BE FILLED
User.19: FIGURE | FINISHED_SIZE | 8.0 | 28.0 | 40.0 | 63.0 | 79.0 | DRILL CHART: TOP to BOTTOM | ALL UNITS ARE IN MILS | TOLERANCE_DRILL | +0.0/-8.0 | +4.0/-0.0 | +3.0/-3.0 | +2.0/-2.0 | +1.0/-2.0 | PLATED | NON-PLATED | QTY | 142 | 8 | 3 | 2 | 4
User.20: Trace Width | (Mils) | Impedance | (Ohms) | Trace Spacing | "Airgap" | L1 | L4 | 5.00 | 50 | 4.2 | 6.00 | 100 | 4.70 | 90 | Layers | Single Ended | Differential
User.21: 2
